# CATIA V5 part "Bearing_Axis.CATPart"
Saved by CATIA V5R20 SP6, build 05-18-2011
Part number: Bearing_Axis
Bounding box of the stored display mesh (mm): x 0 to 10, y -1.992 to 1.992, z -1.992 to 1.992
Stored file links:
  E:\#01 CATIA Lecture Materials\#06 DMU\#16 DMU Page01 KIN EX16\Bearing_Axis.CATPart
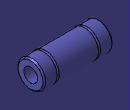
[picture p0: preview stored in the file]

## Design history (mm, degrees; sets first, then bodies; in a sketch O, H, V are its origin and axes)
Set1
  Point1: (0, 0, 0)
Body1 (main body)
  Sketch1 on zx-plane, origin (0, 0, 0), H (-1, 0, 0), V (0, 0, 1)
    axis line L1 (0, 0) -> (-10, 0)
    point P1 (-10, 0)
    line L2 (0, 1) -> (0, 2)
    line L3 (0, 2) -> (-1.85, 2)
    line L4 (-10, 2) -> (-10, 1)
    point P4 (-10, 0)
    arc A1 centre (-8, 2) radius 0.15 from (-8.15, 2) to (-7.85, 2) ccw
    point P5 (-8, 2)
    arc A2 centre (-2, 2) radius 0.15 from (-2.15, 2) to (-1.85, 2) ccw
    point P6 (-2, 2)
    point P7 (-7.85, 2)
    line L5 (-8.15, 2) -> (-10, 2)
    point P8 (-8.15, 2)
    point P9 (-8.15, 2)
    point P10 (-7.85, 2)
    point P11 (-1.85, 2)
    line L6 (-2.15, 2) -> (-7.85, 2)
    point P12 (-2.15, 2)
    point P13 (-2.15, 2)
    point P14 (-1.85, 2)
    line L7 (-10, 1) -> (0, 1)
    distance L3 H = 2
    distance L4 L2 = 10
    radius A2 = 0.15
    radius A1 = 0.15
    distance L2 P6 = 2
    distance L4 P5 = 2
    distance H L7 = 1
    horizontal: L1 H, L3 H, L5 H, L6 H, L7 H
    vertical: L2 V, L4 V
    coincidence: P4 H, P1 P4, P5 L3, P6 L3, A1 P7, A1 P8, L3 L5, L3 P10, L5 P9, A2 P11, A2 P12, L3 L6, L3 P14, L6 P13, P7 P10, P8 P9, P11 P14, P12 P13, L2 V
  Shaft1: profile Sketch1, axis Sketch1.L1, angle 360
  Chamfer1: length 0.2, angle 45, on edge [face of Shaft1 from Sketch1.L5 | face of Shaft1 from Sketch1.L4]; edge [face of Shaft1 from Sketch1.L2 | face of Shaft1 from Sketch1.L3]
